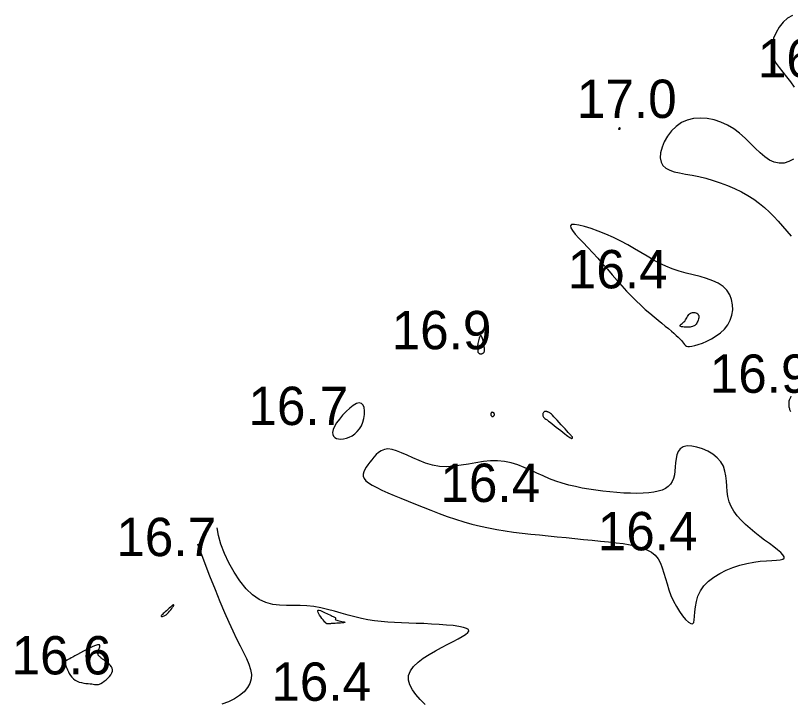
# Model space of a CAD drawing. Extents: x 3040093 to 3056816, y 408076 to 509144.
# Drawn here: x 3045605.9 to 3045706.9, y 434548.5 to 434638.2 of the extents above; entities that cross this region are included whole.
import ezdxf

# ---------------------------------------------------------------- set-up
doc = ezdxf.new("R2010")
doc.units = 0
doc.layers.add('V-CHAN-CONT-EL17', color=7, linetype='Continuous')
doc.layers.add('V-TOPO-SOUN-0610', color=7, linetype='Continuous')

msp = doc.modelspace()

# ---------------------------------------------------------------- linework, layer by layer
at = {"layer": 'V-CHAN-CONT-EL17'}
for points in [[(3045707.19, 434638.16), (3045706.56, 434637.79), (3045705.98, 434637.28), (3045705.48, 434636.65), (3045705.05, 434635.95), (3045704.73, 434635.21), (3045704.53, 434634.47), (3045704.47, 434633.76), (3045704.55, 434633.1), (3045704.76, 434632.5), (3045705.08, 434631.92), (3045705.48, 434631.36), (3045705.94, 434630.78), (3045706.43, 434630.18), (3045706.93, 434629.53), (3045707.41, 434628.82)], [(3045707.31, 434619.42), (3045706.72, 434619.11), (3045706.11, 434618.93), (3045705.47, 434618.89), (3045704.83, 434619.02), (3045704.21, 434619.31), (3045703.59, 434619.73), (3045702.98, 434620.26), (3045702.35, 434620.87), (3045701.7, 434621.52), (3045701.02, 434622.17), (3045700.3, 434622.8), (3045699.54, 434623.38), (3045698.72, 434623.87), (3045697.85, 434624.26), (3045696.97, 434624.55), (3045696.07, 434624.73), (3045695.18, 434624.79), (3045694.31, 434624.73), (3045693.49, 434624.53), (3045692.73, 434624.19), (3045692.03, 434623.71), (3045691.42, 434623.11), (3045690.9, 434622.43), (3045690.49, 434621.71), (3045690.19, 434620.98), (3045690.01, 434620.27), (3045689.96, 434619.61), (3045690.06, 434619.05), (3045690.3, 434618.6), (3045690.68, 434618.26), (3045691.19, 434618), (3045691.79, 434617.8), (3045692.49, 434617.64), (3045693.27, 434617.49), (3045694.11, 434617.34), (3045695, 434617.16), (3045695.91, 434616.94), (3045696.85, 434616.67), (3045697.79, 434616.35), (3045698.73, 434615.99), (3045699.65, 434615.6), (3045700.54, 434615.16), (3045701.39, 434614.7), (3045702.18, 434614.2), (3045702.9, 434613.67), (3045703.57, 434613.12), (3045704.19, 434612.54), (3045704.78, 434611.95), (3045705.35, 434611.33), (3045705.91, 434610.7), (3045706.47, 434610.06), (3045707.04, 434609.41)], [(3045707, 434588.53), (3045706.92, 434588.36), (3045706.84, 434588.2), (3045706.78, 434588.03), (3045706.74, 434587.87), (3045706.71, 434587.71), (3045706.7, 434587.56), (3045706.7, 434587.42), (3045706.71, 434587.28), (3045706.73, 434587.15), (3045706.76, 434587.03), (3045706.79, 434586.91), (3045706.83, 434586.8), (3045706.87, 434586.71), (3045706.91, 434586.62), (3045706.96, 434586.54)], [(3045659.3, 434548.34), (3045658.68, 434548.99), (3045658.11, 434549.63), (3045657.65, 434550.26), (3045657.32, 434550.89), (3045657.14, 434551.51), (3045657.16, 434552.11), (3045657.4, 434552.71), (3045657.81, 434553.28), (3045658.39, 434553.84), (3045659.07, 434554.37), (3045659.84, 434554.87), (3045660.65, 434555.35), (3045661.46, 434555.79), (3045662.25, 434556.2), (3045662.97, 434556.57), (3045663.61, 434556.91), (3045664.15, 434557.21), (3045664.57, 434557.47), (3045664.86, 434557.71), (3045664.99, 434557.92), (3045664.95, 434558.1), (3045664.72, 434558.26), (3045664.3, 434558.4), (3045663.7, 434558.52), (3045662.95, 434558.62), (3045662.09, 434558.7), (3045661.15, 434558.77), (3045660.16, 434558.83), (3045659.15, 434558.88), (3045658.14, 434558.92), (3045657.17, 434558.95), (3045656.24, 434558.98), (3045655.33, 434559.02), (3045654.44, 434559.07), (3045653.57, 434559.15), (3045652.71, 434559.24), (3045651.85, 434559.37), (3045651, 434559.54), (3045650.13, 434559.75), (3045649.26, 434559.99), (3045648.38, 434560.24), (3045647.49, 434560.49), (3045646.6, 434560.73), (3045645.71, 434560.94), (3045644.81, 434561.1), (3045643.91, 434561.2), (3045643.01, 434561.23), (3045642.11, 434561.23), (3045641.22, 434561.23), (3045640.32, 434561.27), (3045639.44, 434561.39), (3045638.55, 434561.63), (3045637.68, 434562.03), (3045636.82, 434562.63), (3045635.98, 434563.44), (3045635.17, 434564.45), (3045634.41, 434565.58), (3045633.73, 434566.79), (3045633.15, 434568.03), (3045632.69, 434569.24), (3045632.37, 434570.37), (3045632.21, 434571.38)], [(3045629.63, 434569.27), (3045630.46, 434567.07), (3045631.22, 434565.1), (3045631.92, 434563.33), (3045632.56, 434561.76), (3045633.16, 434560.35), (3045633.71, 434559.09), (3045634.23, 434557.95), (3045634.72, 434556.92), (3045635.19, 434555.98), (3045635.63, 434555.12), (3045636.01, 434554.32), (3045636.32, 434553.59), (3045636.54, 434552.91), (3045636.66, 434552.27), (3045636.64, 434551.67), (3045636.48, 434551.09), (3045636.17, 434550.54), (3045635.71, 434550.01), (3045635.13, 434549.52), (3045634.44, 434549.08), (3045633.66, 434548.7), (3045632.82, 434548.39)]]:
    msp.add_lwpolyline(points, dxfattribs=at)
for points in [[(3045684.72, 434623.38), (3045684.73, 434623.39), (3045684.73, 434623.41), (3045684.74, 434623.42), (3045684.74, 434623.44), (3045684.74, 434623.46), (3045684.73, 434623.47), (3045684.73, 434623.48), (3045684.72, 434623.49), (3045684.71, 434623.5), (3045684.7, 434623.51), (3045684.69, 434623.51), (3045684.67, 434623.51), (3045684.66, 434623.51), (3045684.64, 434623.51), (3045684.63, 434623.5), (3045684.61, 434623.49), (3045684.6, 434623.48), (3045684.59, 434623.47), (3045684.58, 434623.46), (3045684.57, 434623.45), (3045684.56, 434623.44), (3045684.55, 434623.43), (3045684.54, 434623.42), (3045684.54, 434623.4), (3045684.53, 434623.4), (3045684.52, 434623.39), (3045684.52, 434623.38), (3045684.52, 434623.37), (3045684.52, 434623.36), (3045684.52, 434623.36), (3045684.52, 434623.36), (3045684.52, 434623.35), (3045684.53, 434623.35), (3045684.53, 434623.35), (3045684.54, 434623.35), (3045684.55, 434623.35), (3045684.56, 434623.35), (3045684.58, 434623.35), (3045684.59, 434623.35), (3045684.61, 434623.35), (3045684.62, 434623.35), (3045684.64, 434623.35), (3045684.65, 434623.35), (3045684.67, 434623.35), (3045684.69, 434623.35), (3045684.7, 434623.36), (3045684.71, 434623.36)], [(3045699.08, 434598.45), (3045699.3, 434599.1), (3045699.4, 434599.78), (3045699.39, 434600.46), (3045699.26, 434601.13), (3045699.01, 434601.76), (3045698.64, 434602.34), (3045698.15, 434602.84), (3045697.53, 434603.25), (3045696.81, 434603.59), (3045696.01, 434603.88), (3045695.15, 434604.13), (3045694.25, 434604.36), (3045693.33, 434604.59), (3045692.42, 434604.84), (3045691.52, 434605.13), (3045690.67, 434605.48), (3045689.84, 434605.87), (3045689.04, 434606.31), (3045688.24, 434606.77), (3045687.43, 434607.26), (3045686.6, 434607.75), (3045685.73, 434608.25), (3045684.82, 434608.74), (3045683.85, 434609.21), (3045682.86, 434609.65), (3045681.88, 434610.05), (3045680.94, 434610.39), (3045680.09, 434610.66), (3045679.36, 434610.84), (3045678.79, 434610.92), (3045678.41, 434610.9), (3045678.25, 434610.74), (3045678.3, 434610.48), (3045678.52, 434610.12), (3045678.88, 434609.67), (3045679.35, 434609.14), (3045679.91, 434608.55), (3045680.53, 434607.91), (3045681.17, 434607.23), (3045681.81, 434606.53), (3045682.45, 434605.8), (3045683.08, 434605.07), (3045683.71, 434604.34), (3045684.34, 434603.62), (3045684.96, 434602.91), (3045685.58, 434602.23), (3045686.2, 434601.58), (3045686.81, 434600.96), (3045687.42, 434600.39), (3045688.01, 434599.85), (3045688.59, 434599.35), (3045689.15, 434598.89), (3045689.67, 434598.46), (3045690.17, 434598.05), (3045690.62, 434597.68), (3045691.04, 434597.34), (3045691.41, 434597.02), (3045691.75, 434596.73), (3045692.04, 434596.46), (3045692.3, 434596.21), (3045692.53, 434595.99), (3045692.72, 434595.79), (3045692.88, 434595.6), (3045693.01, 434595.43), (3045693.13, 434595.28), (3045693.25, 434595.16), (3045693.39, 434595.07), (3045693.56, 434595.02), (3045693.78, 434595.01), (3045694.07, 434595.04), (3045694.45, 434595.12), (3045694.91, 434595.26), (3045695.45, 434595.45), (3045696.03, 434595.7), (3045696.64, 434596.01), (3045697.24, 434596.38), (3045697.81, 434596.8), (3045698.33, 434597.29), (3045698.76, 434597.84)], [(3045693.26, 434598.47), (3045693.35, 434598.61), (3045693.43, 434598.76), (3045693.51, 434598.91), (3045693.59, 434599.04), (3045693.68, 434599.17), (3045693.78, 434599.28), (3045693.89, 434599.36), (3045694.02, 434599.42), (3045694.17, 434599.46), (3045694.32, 434599.46), (3045694.46, 434599.44), (3045694.6, 434599.4), (3045694.73, 434599.34), (3045694.84, 434599.26), (3045694.92, 434599.15), (3045694.97, 434599.03), (3045694.99, 434598.9), (3045694.98, 434598.75), (3045694.95, 434598.6), (3045694.91, 434598.46), (3045694.85, 434598.31), (3045694.78, 434598.17), (3045694.71, 434598.05), (3045694.64, 434597.94), (3045694.56, 434597.84), (3045694.47, 434597.76), (3045694.38, 434597.7), (3045694.27, 434597.65), (3045694.15, 434597.6), (3045694.01, 434597.57), (3045693.85, 434597.55), (3045693.67, 434597.54), (3045693.47, 434597.54), (3045693.27, 434597.54), (3045693.08, 434597.55), (3045692.9, 434597.57), (3045692.75, 434597.59), (3045692.63, 434597.63), (3045692.56, 434597.67), (3045692.53, 434597.72), (3045692.56, 434597.77), (3045692.62, 434597.84), (3045692.7, 434597.92), (3045692.81, 434598), (3045692.92, 434598.1), (3045693.04, 434598.21), (3045693.16, 434598.33)], [(3045666.25, 434594.17), (3045666.29, 434594.13), (3045666.34, 434594.11), (3045666.39, 434594.09), (3045666.45, 434594.07), (3045666.51, 434594.06), (3045666.57, 434594.06), (3045666.63, 434594.06), (3045666.69, 434594.06), (3045666.74, 434594.08), (3045666.79, 434594.1), (3045666.84, 434594.12), (3045666.89, 434594.15), (3045666.93, 434594.19), (3045666.96, 434594.23), (3045666.99, 434594.28), (3045667.01, 434594.33), (3045667.03, 434594.4), (3045667.04, 434594.47), (3045667.04, 434594.56), (3045667.04, 434594.67), (3045667.03, 434594.79), (3045667.01, 434594.93), (3045666.99, 434595.1), (3045666.96, 434595.29), (3045666.92, 434595.5), (3045666.88, 434595.7), (3045666.83, 434595.9), (3045666.77, 434596.08), (3045666.72, 434596.23), (3045666.66, 434596.34), (3045666.6, 434596.39), (3045666.53, 434596.38), (3045666.47, 434596.32), (3045666.41, 434596.21), (3045666.35, 434596.08), (3045666.3, 434595.92), (3045666.25, 434595.74), (3045666.21, 434595.57), (3045666.19, 434595.41), (3045666.17, 434595.27), (3045666.15, 434595.15), (3045666.15, 434595.04), (3045666.15, 434594.95), (3045666.15, 434594.86), (3045666.16, 434594.79), (3045666.17, 434594.72), (3045666.17, 434594.66), (3045666.17, 434594.59), (3045666.17, 434594.53), (3045666.17, 434594.47), (3045666.17, 434594.41), (3045666.17, 434594.35), (3045666.18, 434594.3), (3045666.2, 434594.25), (3045666.22, 434594.21)], [(3045651.2, 434585.14), (3045651.34, 434585.64), (3045651.41, 434586.14), (3045651.42, 434586.62), (3045651.35, 434587.04), (3045651.22, 434587.37), (3045651.01, 434587.59), (3045650.72, 434587.66), (3045650.36, 434587.57), (3045649.93, 434587.34), (3045649.48, 434586.99), (3045649, 434586.55), (3045648.55, 434586.07), (3045648.13, 434585.55), (3045647.77, 434585.05), (3045647.5, 434584.58), (3045647.33, 434584.17), (3045647.25, 434583.82), (3045647.27, 434583.54), (3045647.37, 434583.31), (3045647.53, 434583.14), (3045647.76, 434583.02), (3045648.03, 434582.96), (3045648.34, 434582.94), (3045648.68, 434582.97), (3045649.04, 434583.05), (3045649.41, 434583.19), (3045649.78, 434583.37), (3045650.13, 434583.61), (3045650.46, 434583.91), (3045650.76, 434584.26), (3045651.01, 434584.67)], [(3045668.18, 434585.9), (3045668.22, 434585.93), (3045668.26, 434585.97), (3045668.29, 434586.01), (3045668.32, 434586.06), (3045668.34, 434586.11), (3045668.35, 434586.16), (3045668.35, 434586.21), (3045668.33, 434586.25), (3045668.31, 434586.29), (3045668.29, 434586.32), (3045668.25, 434586.35), (3045668.22, 434586.37), (3045668.18, 434586.39), (3045668.14, 434586.4), (3045668.1, 434586.41), (3045668.07, 434586.42), (3045668.05, 434586.43), (3045668.02, 434586.43), (3045668, 434586.43), (3045667.98, 434586.42), (3045667.97, 434586.41), (3045667.95, 434586.39), (3045667.94, 434586.37), (3045667.92, 434586.35), (3045667.91, 434586.31), (3045667.89, 434586.28), (3045667.88, 434586.24), (3045667.88, 434586.2), (3045667.88, 434586.16), (3045667.88, 434586.11), (3045667.89, 434586.07), (3045667.9, 434586.03), (3045667.93, 434585.99), (3045667.96, 434585.95), (3045667.99, 434585.92), (3045668.02, 434585.9), (3045668.06, 434585.88), (3045668.1, 434585.88), (3045668.14, 434585.88)], [(3045678.41, 434583.03), (3045678.42, 434583.03), (3045678.43, 434583.03), (3045678.44, 434583.04), (3045678.45, 434583.04), (3045678.46, 434583.04), (3045678.47, 434583.05), (3045678.47, 434583.05), (3045678.48, 434583.06), (3045678.49, 434583.06), (3045678.5, 434583.07), (3045678.51, 434583.07), (3045678.51, 434583.08), (3045678.52, 434583.09), (3045678.53, 434583.1), (3045678.53, 434583.11), (3045678.53, 434583.12), (3045678.53, 434583.13), (3045678.53, 434583.15), (3045678.53, 434583.16), (3045678.52, 434583.18), (3045678.52, 434583.2), (3045678.51, 434583.21), (3045678.5, 434583.22), (3045678.49, 434583.24), (3045678.47, 434583.25), (3045678.44, 434583.28), (3045678.4, 434583.33), (3045678.34, 434583.39), (3045678.25, 434583.49), (3045678.13, 434583.62), (3045677.97, 434583.79), (3045677.78, 434584.01), (3045677.55, 434584.26), (3045677.31, 434584.54), (3045677.05, 434584.82), (3045676.79, 434585.11), (3045676.54, 434585.39), (3045676.31, 434585.64), (3045676.1, 434585.86), (3045675.92, 434586.04), (3045675.77, 434586.18), (3045675.65, 434586.28), (3045675.56, 434586.36), (3045675.47, 434586.41), (3045675.41, 434586.44), (3045675.35, 434586.47), (3045675.29, 434586.49), (3045675.23, 434586.51), (3045675.17, 434586.52), (3045675.11, 434586.54), (3045675.06, 434586.54), (3045675, 434586.54), (3045674.94, 434586.54), (3045674.89, 434586.52), (3045674.84, 434586.49), (3045674.79, 434586.45), (3045674.74, 434586.4), (3045674.7, 434586.34), (3045674.67, 434586.26), (3045674.65, 434586.19), (3045674.64, 434586.11), (3045674.64, 434586.03), (3045674.66, 434585.96), (3045674.7, 434585.88), (3045674.75, 434585.81), (3045674.83, 434585.73), (3045674.93, 434585.64), (3045675.05, 434585.54), (3045675.2, 434585.43), (3045675.39, 434585.29), (3045675.6, 434585.13), (3045675.85, 434584.94), (3045676.12, 434584.73), (3045676.41, 434584.5), (3045676.7, 434584.27), (3045676.99, 434584.04), (3045677.27, 434583.83), (3045677.52, 434583.63), (3045677.74, 434583.47), (3045677.92, 434583.33), (3045678.06, 434583.23), (3045678.17, 434583.15), (3045678.25, 434583.1), (3045678.3, 434583.07), (3045678.35, 434583.05), (3045678.37, 434583.04), (3045678.39, 434583.03)], [(3045658.04, 434574.47), (3045659.04, 434574.06), (3045660.07, 434573.66), (3045661.12, 434573.26), (3045662.18, 434572.87), (3045663.26, 434572.5), (3045664.34, 434572.16), (3045665.42, 434571.85), (3045666.51, 434571.58), (3045667.59, 434571.35), (3045668.67, 434571.15), (3045669.76, 434570.98), (3045670.85, 434570.82), (3045671.96, 434570.69), (3045673.08, 434570.56), (3045674.21, 434570.44), (3045675.36, 434570.33), (3045676.52, 434570.21), (3045677.68, 434570.1), (3045678.83, 434569.98), (3045679.97, 434569.87), (3045681.08, 434569.76), (3045682.16, 434569.65), (3045683.21, 434569.54), (3045684.2, 434569.43), (3045685.14, 434569.31), (3045686.02, 434569.17), (3045686.83, 434569), (3045687.57, 434568.79), (3045688.23, 434568.52), (3045688.81, 434568.2), (3045689.29, 434567.8), (3045689.67, 434567.32), (3045689.98, 434566.76), (3045690.23, 434566.15), (3045690.44, 434565.48), (3045690.64, 434564.78), (3045690.84, 434564.05), (3045691.07, 434563.31), (3045691.34, 434562.56), (3045691.67, 434561.82), (3045692.06, 434561.12), (3045692.46, 434560.47), (3045692.87, 434559.89), (3045693.27, 434559.42), (3045693.64, 434559.08), (3045693.94, 434558.88), (3045694.18, 434558.86), (3045694.32, 434559.03), (3045694.4, 434559.36), (3045694.44, 434559.83), (3045694.48, 434560.41), (3045694.55, 434561.06), (3045694.67, 434561.75), (3045694.87, 434562.46), (3045695.2, 434563.15), (3045695.66, 434563.8), (3045696.25, 434564.4), (3045696.94, 434564.94), (3045697.72, 434565.43), (3045698.56, 434565.86), (3045699.44, 434566.22), (3045700.35, 434566.52), (3045701.26, 434566.74), (3045702.15, 434566.9), (3045703, 434567.01), (3045703.79, 434567.07), (3045704.5, 434567.12), (3045705.1, 434567.16), (3045705.59, 434567.21), (3045705.93, 434567.29), (3045706.11, 434567.42), (3045706.11, 434567.61), (3045705.96, 434567.86), (3045705.66, 434568.17), (3045705.25, 434568.51), (3045704.75, 434568.9), (3045704.18, 434569.33), (3045703.56, 434569.78), (3045702.92, 434570.26), (3045702.28, 434570.76), (3045701.66, 434571.27), (3045701.06, 434571.8), (3045700.5, 434572.36), (3045699.99, 434572.93), (3045699.55, 434573.53), (3045699.19, 434574.14), (3045698.93, 434574.78), (3045698.76, 434575.44), (3045698.67, 434576.11), (3045698.62, 434576.79), (3045698.58, 434577.47), (3045698.51, 434578.13), (3045698.39, 434578.78), (3045698.19, 434579.39), (3045697.86, 434579.96), (3045697.4, 434580.49), (3045696.81, 434580.96), (3045696.15, 434581.35), (3045695.45, 434581.67), (3045694.74, 434581.9), (3045694.06, 434582.03), (3045693.45, 434582.04), (3045692.94, 434581.93), (3045692.56, 434581.69), (3045692.29, 434581.34), (3045692.12, 434580.9), (3045692.02, 434580.4), (3045691.96, 434579.86), (3045691.92, 434579.31), (3045691.88, 434578.76), (3045691.81, 434578.26), (3045691.7, 434577.8), (3045691.52, 434577.4), (3045691.29, 434577.05), (3045691, 434576.76), (3045690.64, 434576.51), (3045690.21, 434576.3), (3045689.7, 434576.14), (3045689.12, 434576.02), (3045688.45, 434575.93), (3045687.72, 434575.88), (3045686.92, 434575.86), (3045686.08, 434575.87), (3045685.2, 434575.91), (3045684.29, 434575.97), (3045683.38, 434576.05), (3045682.46, 434576.15), (3045681.56, 434576.26), (3045680.67, 434576.4), (3045679.78, 434576.55), (3045678.91, 434576.74), (3045678.05, 434576.95), (3045677.19, 434577.19), (3045676.35, 434577.47), (3045675.52, 434577.78), (3045674.69, 434578.14), (3045673.87, 434578.51), (3045673.04, 434578.89), (3045672.21, 434579.25), (3045671.38, 434579.57), (3045670.52, 434579.84), (3045669.65, 434580.03), (3045668.76, 434580.12), (3045667.84, 434580.11), (3045666.9, 434580.02), (3045665.94, 434579.86), (3045664.98, 434579.69), (3045664.01, 434579.53), (3045663.05, 434579.4), (3045662.1, 434579.34), (3045661.17, 434579.38), (3045660.25, 434579.54), (3045659.37, 434579.8), (3045658.52, 434580.13), (3045657.71, 434580.48), (3045656.95, 434580.84), (3045656.24, 434581.17), (3045655.59, 434581.43), (3045655, 434581.6), (3045654.47, 434581.65), (3045654.01, 434581.58), (3045653.6, 434581.43), (3045653.24, 434581.2), (3045652.91, 434580.91), (3045652.62, 434580.59), (3045652.35, 434580.25), (3045652.09, 434579.91), (3045651.84, 434579.58), (3045651.62, 434579.27), (3045651.43, 434578.96), (3045651.3, 434578.67), (3045651.23, 434578.38), (3045651.25, 434578.1), (3045651.37, 434577.81), (3045651.6, 434577.52), (3045651.95, 434577.23), (3045652.42, 434576.92), (3045653, 434576.61), (3045653.68, 434576.29), (3045654.43, 434575.95), (3045655.26, 434575.6), (3045656.14, 434575.24), (3045657.08, 434574.86)], [(3045624.94, 434559.82), (3045625, 434559.81), (3045625.07, 434559.82), (3045625.17, 434559.84), (3045625.28, 434559.89), (3045625.4, 434559.95), (3045625.54, 434560.05), (3045625.69, 434560.17), (3045625.84, 434560.33), (3045626, 434560.5), (3045626.15, 434560.68), (3045626.29, 434560.87), (3045626.4, 434561.03), (3045626.49, 434561.17), (3045626.54, 434561.28), (3045626.54, 434561.33), (3045626.49, 434561.33), (3045626.39, 434561.27), (3045626.26, 434561.17), (3045626.11, 434561.04), (3045625.94, 434560.89), (3045625.76, 434560.73), (3045625.59, 434560.57), (3045625.42, 434560.43), (3045625.28, 434560.3), (3045625.16, 434560.19), (3045625.06, 434560.09), (3045624.99, 434560.02), (3045624.93, 434559.96), (3045624.9, 434559.91), (3045624.89, 434559.87), (3045624.9, 434559.84)], [(3045646.65, 434558.84), (3045646.61, 434558.84), (3045646.56, 434558.85), (3045646.5, 434558.87), (3045646.43, 434558.92), (3045646.35, 434558.98), (3045646.25, 434559.08), (3045646.13, 434559.21), (3045646, 434559.38), (3045645.85, 434559.57), (3045645.7, 434559.77), (3045645.56, 434559.98), (3045645.44, 434560.18), (3045645.36, 434560.35), (3045645.31, 434560.5), (3045645.32, 434560.59), (3045645.38, 434560.64), (3045645.49, 434560.63), (3045645.65, 434560.59), (3045645.83, 434560.51), (3045646.04, 434560.42), (3045646.26, 434560.31), (3045646.48, 434560.2), (3045646.69, 434560.1), (3045646.88, 434560.01), (3045647.05, 434559.93), (3045647.2, 434559.87), (3045647.32, 434559.82), (3045647.43, 434559.77), (3045647.51, 434559.73), (3045647.57, 434559.69), (3045647.61, 434559.65), (3045647.62, 434559.61), (3045647.62, 434559.57), (3045647.61, 434559.53), (3045647.6, 434559.49), (3045647.61, 434559.44), (3045647.64, 434559.4), (3045647.69, 434559.36), (3045647.79, 434559.32), (3045647.92, 434559.28), (3045648.09, 434559.24), (3045648.28, 434559.2), (3045648.46, 434559.17), (3045648.62, 434559.13), (3045648.76, 434559.1), (3045648.84, 434559.07), (3045648.86, 434559.04), (3045648.8, 434559.02), (3045648.67, 434559), (3045648.5, 434558.98), (3045648.28, 434558.96), (3045648.05, 434558.94), (3045647.81, 434558.93), (3045647.58, 434558.91), (3045647.37, 434558.9), (3045647.2, 434558.89), (3045647.06, 434558.88), (3045646.96, 434558.87), (3045646.88, 434558.86), (3045646.81, 434558.86), (3045646.77, 434558.85), (3045646.73, 434558.85), (3045646.69, 434558.84)], [(3045612.6, 434553.06), (3045612.69, 434552.85), (3045612.8, 434552.61), (3045612.93, 434552.37), (3045613.09, 434552.13), (3045613.27, 434551.9), (3045613.47, 434551.7), (3045613.7, 434551.52), (3045613.95, 434551.38), (3045614.23, 434551.27), (3045614.52, 434551.19), (3045614.81, 434551.14), (3045615.1, 434551.1), (3045615.37, 434551.07), (3045615.63, 434551.05), (3045615.85, 434551.03), (3045616.04, 434551), (3045616.19, 434550.97), (3045616.33, 434550.94), (3045616.46, 434550.93), (3045616.59, 434550.93), (3045616.72, 434550.96), (3045616.87, 434551.01), (3045617.05, 434551.1), (3045617.26, 434551.22), (3045617.49, 434551.38), (3045617.73, 434551.57), (3045617.96, 434551.77), (3045618.17, 434551.99), (3045618.35, 434552.22), (3045618.49, 434552.45), (3045618.56, 434552.67), (3045618.57, 434552.88), (3045618.52, 434553.08), (3045618.41, 434553.27), (3045618.27, 434553.45), (3045618.11, 434553.6), (3045617.93, 434553.75), (3045617.76, 434553.88), (3045617.6, 434554), (3045617.46, 434554.1), (3045617.34, 434554.19), (3045617.25, 434554.27), (3045617.17, 434554.34), (3045617.1, 434554.4), (3045617.03, 434554.45), (3045616.98, 434554.5), (3045616.92, 434554.55), (3045616.86, 434554.6), (3045616.8, 434554.66), (3045616.75, 434554.72), (3045616.7, 434554.79), (3045616.67, 434554.88), (3045616.65, 434554.97), (3045616.65, 434555.09), (3045616.67, 434555.22), (3045616.72, 434555.38), (3045616.79, 434555.55), (3045616.85, 434555.71), (3045616.89, 434555.87), (3045616.9, 434556), (3045616.86, 434556.1), (3045616.77, 434556.14), (3045616.59, 434556.13), (3045616.34, 434556.05), (3045616.01, 434555.92), (3045615.63, 434555.74), (3045615.22, 434555.53), (3045614.79, 434555.31), (3045614.38, 434555.08), (3045613.99, 434554.87), (3045613.65, 434554.68), (3045613.38, 434554.53), (3045613.16, 434554.41), (3045612.99, 434554.31), (3045612.87, 434554.25), (3045612.77, 434554.2), (3045612.71, 434554.16), (3045612.66, 434554.14), (3045612.61, 434554.11), (3045612.57, 434554.08), (3045612.53, 434554.06), (3045612.48, 434554.03), (3045612.44, 434554), (3045612.41, 434553.97), (3045612.38, 434553.95), (3045612.35, 434553.92), (3045612.32, 434553.9), (3045612.31, 434553.88), (3045612.3, 434553.87), (3045612.29, 434553.85), (3045612.29, 434553.85), (3045612.29, 434553.84), (3045612.29, 434553.83), (3045612.3, 434553.81), (3045612.31, 434553.8), (3045612.31, 434553.79), (3045612.32, 434553.77), (3045612.33, 434553.73), (3045612.35, 434553.68), (3045612.38, 434553.62), (3045612.41, 434553.53), (3045612.46, 434553.4), (3045612.52, 434553.25)]]:
    msp.add_lwpolyline(points, close=True, dxfattribs=at)

# ---------------------------------------------------------------- texts
at = {"layer": 'V-TOPO-SOUN-0610'}
for s, p in [('16.4 ', (3045702.68, 434630.08)), ('17.0 ', (3045679.09, 434624.8)), ('16.4 ', (3045677.91, 434602.59)), ('16.9 ', (3045654.94, 434594.65)), ('16.9 ', (3045696.41, 434588.97)), ('16.7 ', (3045636.27, 434584.77)), ('16.4 ', (3045661.3, 434574.74)), ('16.4 ', (3045681.81, 434568.44)), ('16.7 ', (3045619.05, 434567.68)), ('16.6 ', (3045605.4, 434552.26)), ('16.4 ', (3045639.26, 434548.82))]:
    msp.add_text(s, height=5, dxfattribs=at).set_placement(p)

doc.saveas('drawing.dxf')
